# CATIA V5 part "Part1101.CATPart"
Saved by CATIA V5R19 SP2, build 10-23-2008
Part number: MS_04001 (middle plate v1)
Publications: "Sommet", "Sommet1", "Sommet2", "Sommet3", "Plan.5", "Arête"
Bounding box of the stored display mesh (mm): x -1505.94 to -86.733, y -321.625 to 322.154, z -552.286 to 706.382
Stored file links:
  D:\EPSA\GIT\ELIZ-2022\01 - Maquette CATIA\MS_Miscellanous_Finish_Assembly\MS_A0400 (Firewall)\Part1101.CATPart
  D:\EPSA\GIT\ELIZ-2022\01 - Maquette CATIA\MS_Miscellanous_Finish_Assembly\MS_A0400 (Firewall)\MS_A0400 (FireWall).CATProduct
  D:\EPSA\GIT\ELIZ-2022\01 - Maquette CATIA\FR_Frame_Body\FR_A0100 (frame)\Filaire.CATPart
  D:\EPSA\GIT\ELIZ-2022\01 - Maquette CATIA\FR_Frame_Body\FR_A0100 (frame)\Shape_478.CATPart
  D:\EPSA\GIT\ELIZ-2022\01 - Maquette CATIA\FR_Frame_Body\FR_A0100 (frame)\Shape_354.CATPart
  D:\EPSA\GIT\ELIZ-2022\01 - Maquette CATIA\FR_Frame_Body\FR_A0100 (frame)\Shape_425.CATPart
  D:\EPSA\GIT\ELIZ-2022\01 - Maquette CATIA\FR_Frame_Body\FR_A0100 (frame)\Shape_511.CATPart
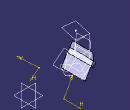
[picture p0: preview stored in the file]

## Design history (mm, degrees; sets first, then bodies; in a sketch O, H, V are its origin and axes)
SheetMetalParameters1: Thickness 1, BendRadius 1, KFactor 0.325257 {= log(min(100,max(20*SheetMetalParameters1.BendRadius,SheetMetalParameters1.Thickness)/SheetMetalParameters1.Thickness))/log(100)/2}, ReliefRadialLength 1, ReliefAxialLength 2, MinimumBendRadius 0
Set1
  Line1: linked copy from another document
  Line2: linked copy from another document
  Line3 "Droite_RSB": linked copy from another document
  Line4 to Line6: linked copy from another document
  DatumCurve1: linked copy from another document
Body1 (main body)
  Line7: stored without definition
  Line8: stored without definition
  Plane1: type 2Lines, Element1 Line7, Element2 Line1
  Sketch1 on Plane1, origin (-1389.7798, 0, -170.6434), H (0, 1, 0), V (-0.1219, 0, 0.9925)
    line L1 (320.7057, 412.345) -> (271.6136, 586.2868)
    line L2 (271.6136, 586.2868) -> (-271.415, 586.2868)
    line L3 (-271.415, 586.2868) -> (-321.1773, 412.345)
    line L4 (-321.1773, 412.345) -> (320.7057, 412.345)
    horizontal: L2 H, L4 H
  Pad1: profile Sketch1, direction (0.9925, 0, 0.1219), length 1
  Plane2: type Normal, Curve Line2
  Sketch2 on Plane2, origin (0, 0, 0), H (-1, 0, 0), V (0, 0, 1)
    circle A1 centre (1462.666, 422.967) radius 15
    point P1 (1462.666, 422.967)
    reference projected point E1 (1462.666, 422.967) from Line2
    radius A1 = 15
    coincidence: P1 E1
  Pocket1: profile Sketch2, direction (0, -1, 0), through (limit type 6), opposite side through (limit type 6)
  Plane3: type Normal, Curve Line3
  Sketch3 on Plane3, origin (-86.7331, 202.5578, 706.3825), H (0.9193, 0.3936, 0), V (0.3758, -0.8776, 0.2978)
    circle A1 centre (-1456.3446, -174.5088) radius 15
    point P1 (-1456.3446, -174.5088)
    reference projected point E1 (-1456.3446, -174.5088) from Line3
    radius A1 = 15
    coincidence: P1 E1
  Line9: type PtPt, FirstPoint vertex [face of Pad1 from Sketch1.L4 | face of Pad1 from Sketch1.L1 | end face of Pad1], SecondPoint vertex [end face of Pad1 | face of Pad1 from Sketch1.L4 | face of Pad1 from Sketch1.L3]
  Plane4: type 2Lines, Element1 Line4, Element2 Line9
  Wall1: Thickness 1, Profile end face of Pad1
  DatumCurve2
  d_NewWallOnEdge1: NewWallOnEdge_Edge edge [face of Wall1 | face of Wall1], KFacteur 0.325257 {= log(min(100,max(20*d_NewWallOnEdge1.Radius,SheetMetalParameters1.Thickness)/SheetMetalParameters1.Thickness))/log(100)/2}, NewWallOnEdge_Length 65, NewWallOnEdge_HeightLimitOffset 0, NewWallOnEdge_WidthOffset1 0, NewWallOnEdge_WidthOffset2 0, NewWallOnEdge_Angle 4, NewWallOnEdge_BendRadiusValue 1 {= SheetMetalParameters1.BendRadius}, NewWallOnEdge_BendTable SheetMetalParameters1, NewWallOnEdge_PlaneSupport Plane4
  d_NewWallOnEdge2: NewWallOnEdge_Edge edge [face of d_NewWallOnEdge1 | face of d_NewWallOnEdge1], KFacteur 0.325257 {= log(min(100,max(20*d_NewWallOnEdge2.Radius,SheetMetalParameters1.Thickness)/SheetMetalParameters1.Thickness))/log(100)/2}, NewWallOnEdge_Length 71, NewWallOnEdge_HeightLimitOffset 0, NewWallOnEdge_WidthOffset1 0, NewWallOnEdge_WidthOffset2 0, NewWallOnEdge_Angle 167, NewWallOnEdge_BendRadiusValue 1 {= SheetMetalParameters1.BendRadius}, NewWallOnEdge_BendTable SheetMetalParameters1
  Plane5: type 2Lines, Element1 Line5, Element2 Line6
  d_NewWallOnEdge3: NewWallOnEdge_Edge edge [face of d_NewWallOnEdge1 | face of d_NewWallOnEdge1], KFacteur 0.325257 {= log(min(100,max(20*d_NewWallOnEdge3.Radius,SheetMetalParameters1.Thickness)/SheetMetalParameters1.Thickness))/log(100)/2}, NewWallOnEdge_Length 73, NewWallOnEdge_HeightLimitOffset 0, NewWallOnEdge_WidthOffset1 0, NewWallOnEdge_WidthOffset2 0, NewWallOnEdge_Angle 90, NewWallOnEdge_BendRadiusValue 1 {= SheetMetalParameters1.BendRadius}, NewWallOnEdge_BendTable SheetMetalParameters1
  d_NewWallOnEdge4: NewWallOnEdge_Edge edge [face of d_NewWallOnEdge1 | face of d_NewWallOnEdge1], KFacteur 0.325257 {= log(min(100,max(20*d_NewWallOnEdge4.Radius,SheetMetalParameters1.Thickness)/SheetMetalParameters1.Thickness))/log(100)/2}, NewWallOnEdge_Length 73, NewWallOnEdge_HeightLimitOffset 0, NewWallOnEdge_WidthOffset1 0, NewWallOnEdge_WidthOffset2 0, NewWallOnEdge_Angle 90, NewWallOnEdge_BendRadiusValue 1 {= SheetMetalParameters1.BendRadius}, NewWallOnEdge_BendTable SheetMetalParameters1
  Plane6: type Normal, Curve DatumCurve1
  Sketch4 on face of d_NewWallOnEdge2, origin (-951.9715, 0, -552.2861), H (0, 1, 0), V (-0.5018, 0, 0.865)
    point P1 (-305.0302, 811.6745)
    line L1 (-305.0302, 811.6745) -> (-277.2244, 675.0939)
    point P2 (-277.2244, 675.0939)
    line L2 (-277.2244, 675.0939) -> (-230.0076, 517.7121)
    point P3 (-230.0076, 517.7121)
    line L3 (-230.0076, 517.7121) -> (230.0076, 517.7121)
    point P4 (230.0076, 517.7121)
    point P5 (305.0302, 811.6745)
    line L4 (305.0302, 811.6745) -> (-305.0302, 811.6745)
    axis line L5 (0, 462.6338) -> (0, 966.3524)
    point P6 (0, 462.6338)
    point P8 (277.2244, 675.0939)
    point P9 (305.0302, 811.6745)
    line L6 (305.0302, 811.6745) -> (277.2244, 675.0939)
    point P10 (230.0076, 517.7121)
    line L7 (277.2244, 675.0939) -> (230.0076, 517.7121)
    horizontal: L3 H, L4 H
    coincidence: P6 V, P4 P10, P5 P9
    vertical: L5 V
    symmetry: P2 P8 L5, P1 P9 L5, L1 L6 L5, P3 P10 L5, L2 L7 L5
